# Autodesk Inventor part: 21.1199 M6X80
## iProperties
Created: 2006-02
Part Number: 21.1199 M6X80
Material: Steel, Mild
Description: Cylinder Head Cap Screw
Document SubType Name: Modeling
Standard: DIN 7984
Designer: Andy Moles
Standards Organization: DIN
Language: en-US
Size Designation: M6 x 40
Categories: <MemberInstance><Categories><Category DisplayName="Fasteners" InternalName="e4da775c-781d-43d5-af7c-5136215cf5a6" Mnemonic="FSTN"><Category DisplayName="Bolts"
Density: 1 g/cm^3
Author: Andy Moles
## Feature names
1. Body [Revolution]
2. Slot [Extrusion]
3. Fillet1
4. Chamfer1
